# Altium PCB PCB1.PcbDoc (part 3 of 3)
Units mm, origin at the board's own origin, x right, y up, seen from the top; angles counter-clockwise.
Board outline 200.72 x 147.2 mm, 4 copper layers (L1 - TOP, L2 - GND, L3 - PWR, L4 - BOTTOM), stack 1.251 mm thick; 298 components, 161 nets, 911 pads, 474 vias.
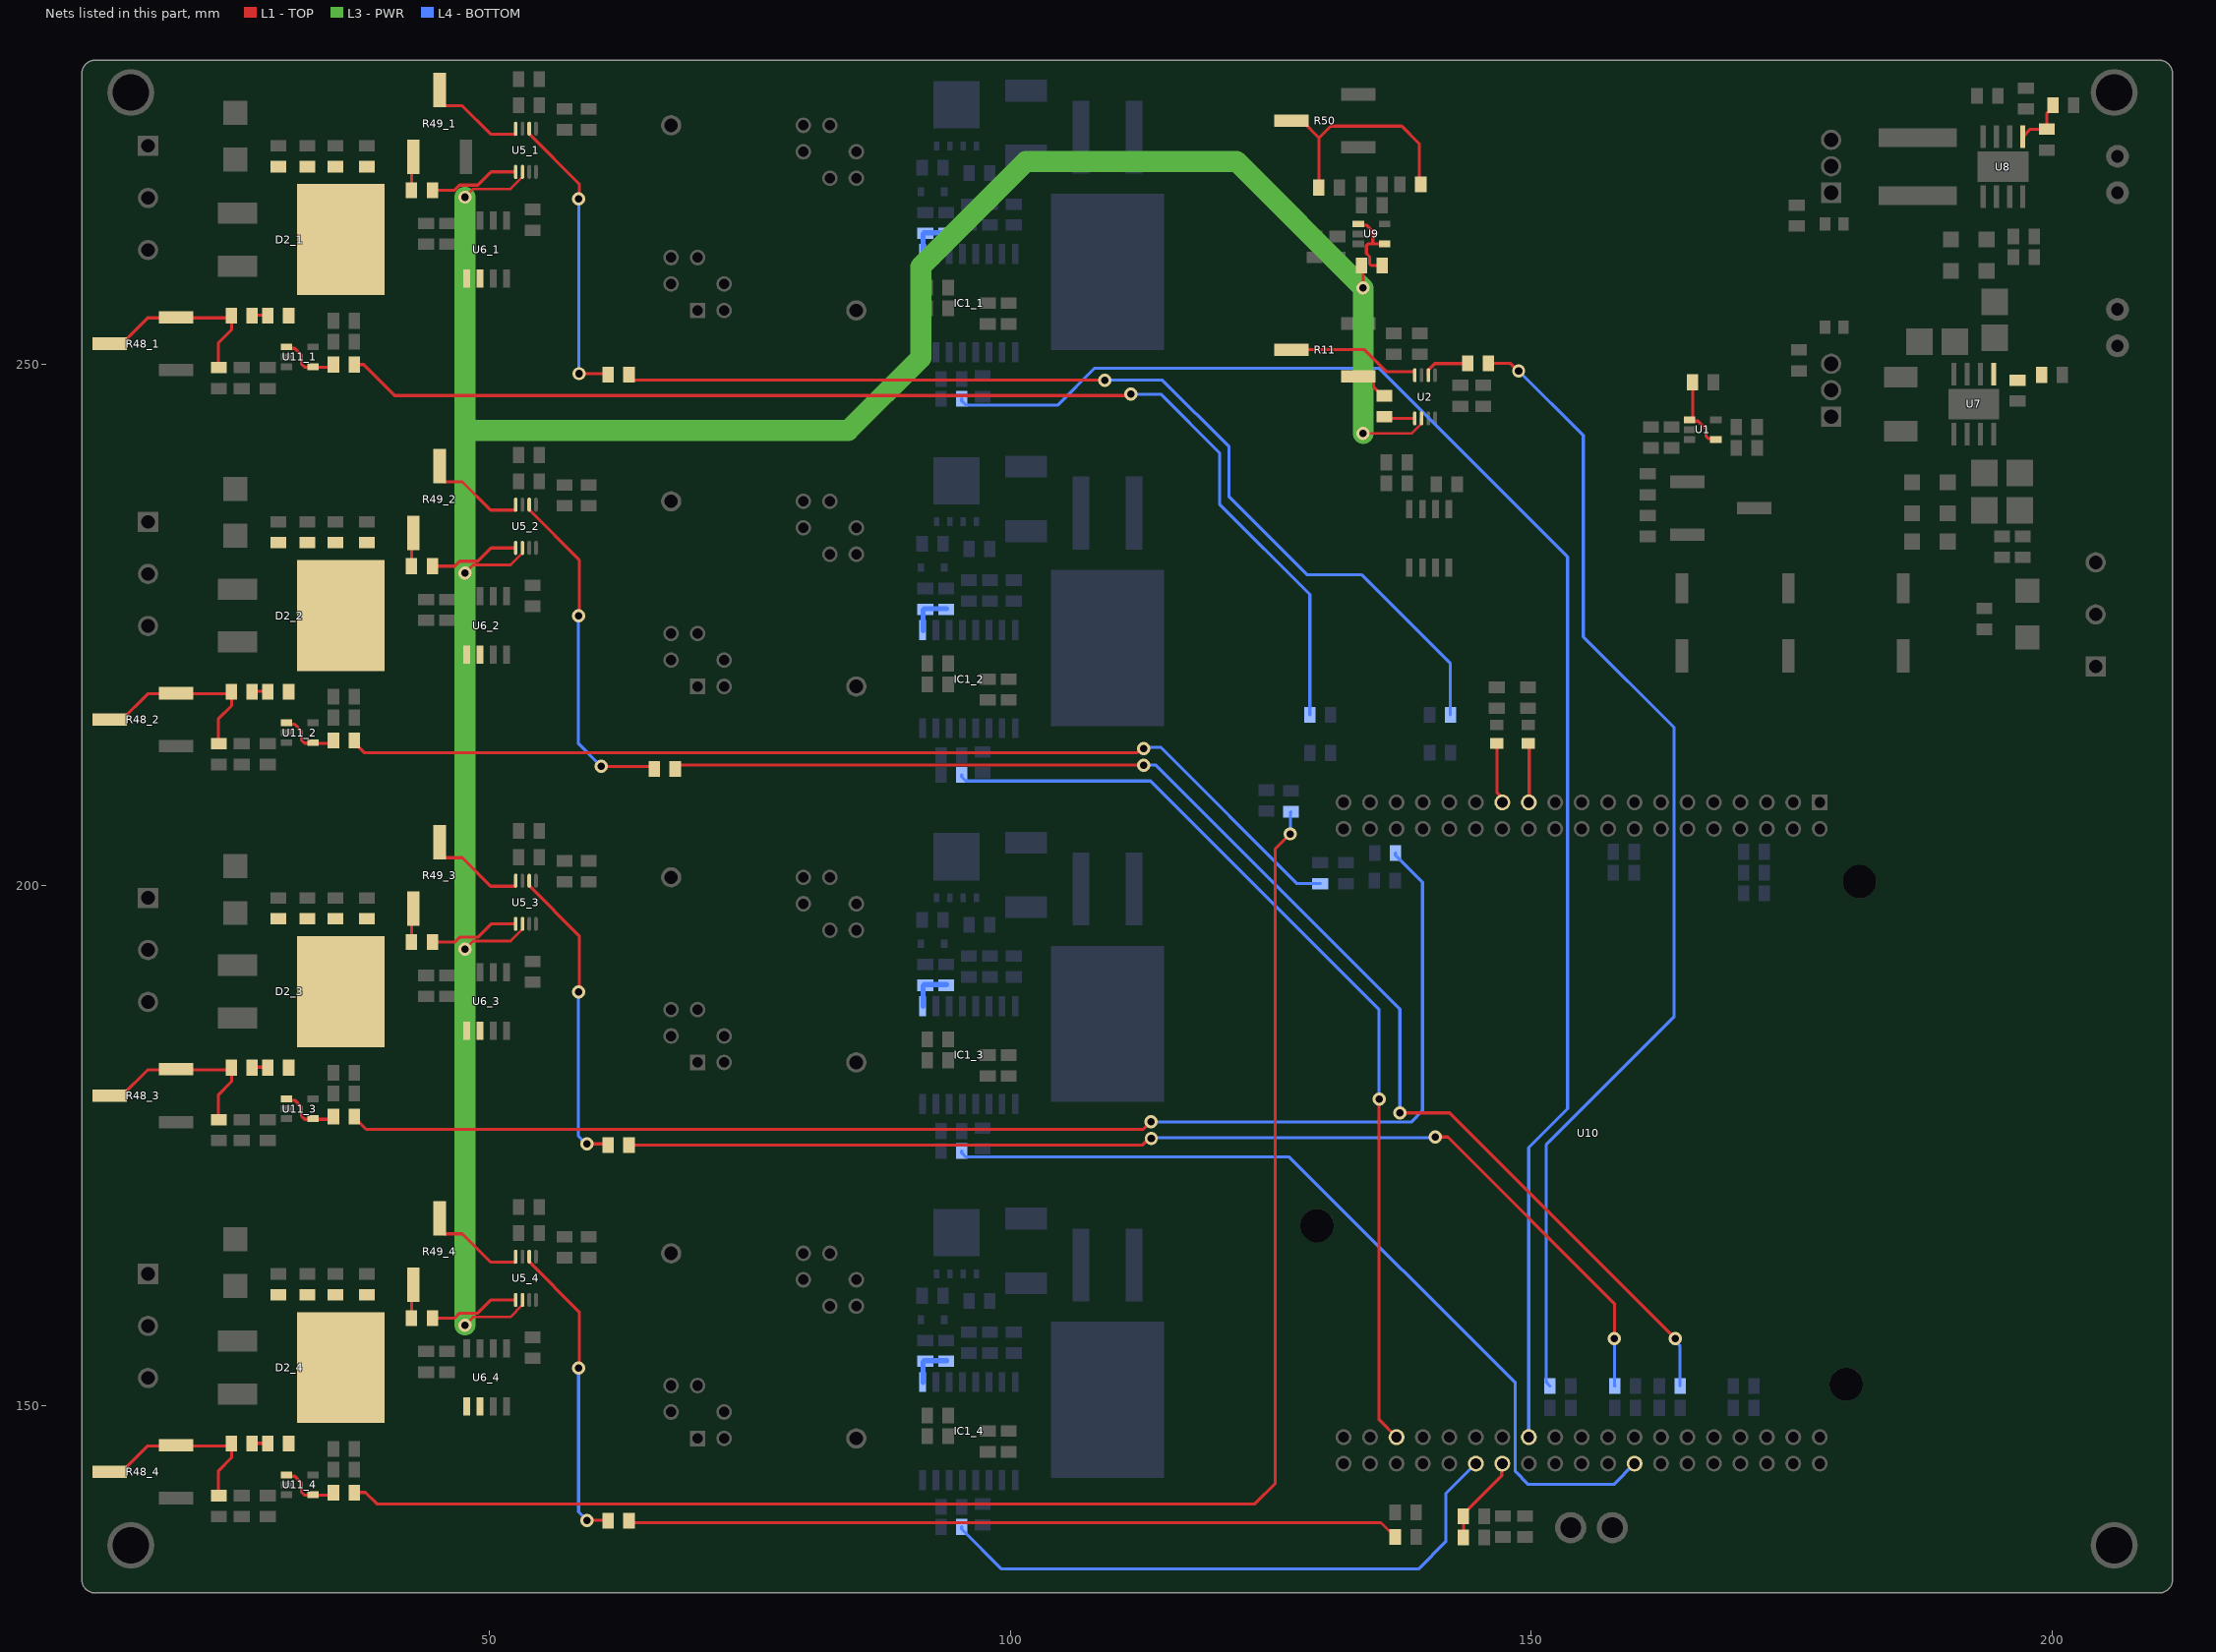
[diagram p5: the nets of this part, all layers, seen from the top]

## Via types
v1: diameter 0.8, hole 0.4, L1 - TOP to L4 - BOTTOM, tented both sides, 312 vias
v2: diameter 1.27, hole 0.711, L1 - TOP to L4 - BOTTOM, 150 vias
v3: diameter 0.63, hole 0.33, L1 - TOP to L4 - BOTTOM, 12 vias

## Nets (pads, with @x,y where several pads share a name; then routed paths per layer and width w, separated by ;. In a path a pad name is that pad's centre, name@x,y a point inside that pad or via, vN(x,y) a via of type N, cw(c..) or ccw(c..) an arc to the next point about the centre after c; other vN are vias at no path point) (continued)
NetR3_2: R3.2 U1.1 U1.4 | length 7.4
  L1 - TOP w0.3: U1.1@165.25,244.75 165.425,244.575 166.025,244.575 166.8,243.8 166.8,243.076 166.976,242.9 167.735,242.9 U1.4@167.79,242.845 ; U1.1@165.325,244.75 165.5,244.925 R3.2@165.5,248.3
NetR6_1: R6.1 R11.1 | length 3.7
  L1 - TOP w0.3: R11.1@133.375,248.91 134.43,248.91 134.875,248.465 134.875,247.813 135.688,247 R6.1@135.9,247
NetR6_2: R6.2 U2.1 | length 3
  L1 - TOP w0.3: R6.2@135.9,245 136.075,244.825 U2.1@138.825,244.825
NetR7_1: R7.1 R8.2 | length 112.1
  L1 - TOP w0.3: R7.1@145.925,250.125 147.991,250.125 148.716,249.4 v2(148.8,249.4)
  L4 - BOTTOM w0.3: v2(148.8,249.4) 155,243.2 155,223.85 163.725,215.125 163.725,187.375 151.45,175.1 151.45,152.25 R8.2@151.8,151.9
NetR7_2: R7.2 U2.6 | length 4.5
  L1 - TOP w0.3: U2.6@140.125,248.975 140.125,249.475 140.75,250.1 R7.2@143.9,250.1
NetR11_2: R11.2 U2.8 | length 13.1
  L1 - TOP w0.3: R11.2@126.975,251.45 133.95,251.45 136.075,249.325 138.802,249.325 138.825,249.302 U2.8@138.825,248.975
NetR13_1_2: R13_1.2 U10.CN10_23 | length 153.6
  L4 - BOTTOM w0.3: R13_1.2@95.325,246.7 95.325,246.51 95.725,246.11 104.56,246.11 108.1,249.65 135.375,249.65 153.5,231.525 153.5,178.532 149.77,174.802 U10.CN10_23@149.77,146.99
NetR13_2_2: R13_2.2 U10.CN10_33 | length 91.3
  L1 - TOP w0.3: v2(135.4,179.45) 135.4,148.66 U10.CN10_33@137.07,146.99
  L4 - BOTTOM w0.3: R13_2.2@95.325,210.59 95.325,210.4 95.725,210 113.46,210 135.4,188.06 v2(135.4,179.45)
NetR13_3_2: R13_3.2 U10.CN10_16 | length 83.8
  L4 - BOTTOM w0.3: R13_3.2@95.325,174.48 95.325,174.29 95.725,173.89 126.785,173.89 148.475,152.2 148.475,143.7 149.725,142.45 157.93,142.45 U10.CN10_16@159.93,144.45
NetR13_4_2: R13_4.2 U10.CN10_28 | length 58.1
  L4 - BOTTOM w0.3: R13_4.2@95.325,138.37 95.325,138.158 99.159,134.324 139.174,134.324 141.8,136.95 141.8,141.56 U10.CN10_28@144.69,144.45
NetR16_1_1: R16_1.1 R17_1.2 | length 1.6
  L1 - TOP w0.3: R17_1.2@27.228,254.734 R16_1.1@28.791,254.734
NetR16_2_1: R16_2.1 R17_2.2 | length 1.6
  L1 - TOP w0.3: R17_2.2@27.228,218.624 R16_2.1@28.791,218.624
NetR16_3_1: R16_3.1 R17_3.2 | length 1.6
  L1 - TOP w0.3: R17_3.2@27.228,182.514 R16_3.1@28.791,182.514
NetR16_4_1: R16_4.1 R17_4.2 | length 1.6
  L1 - TOP w0.3: R17_4.2@27.228,146.404 R16_4.1@28.791,146.404
NetR17_1_1: R17_1.1 R20_1.2 R48_1.2 R48_1.3 | length 18.4
  L1 - TOP w0.3: R48_1.2@13.585,251.944 14.64,251.944 17.18,254.484 19.985,254.484 24.978,254.484 25.228,254.734 25.228,253.356 23.966,252.094 R20_1.2@23.966,249.686
NetR17_2_1: R17_2.1 R20_2.2 R48_2.2 R48_2.3 | length 18.4
  L1 - TOP w0.3: R48_2.2@13.585,215.834 14.64,215.834 17.18,218.374 19.985,218.374 24.978,218.374 25.228,218.624 25.228,217.246 23.966,215.984 R20_2.2@23.966,213.576
NetR17_3_1: R17_3.1 R20_3.2 R48_3.2 R48_3.3 | length 18.4
  L1 - TOP w0.3: R48_3.2@13.585,179.724 14.64,179.724 17.18,182.264 19.985,182.264 24.978,182.264 25.228,182.514 25.228,181.136 23.966,179.874 R20_3.2@23.966,177.466
NetR17_4_1: R17_4.1 R20_4.2 R48_4.2 R48_4.3 | length 18.4
  L1 - TOP w0.3: R48_4.2@13.585,143.614 14.64,143.614 17.18,146.154 19.985,146.154 24.978,146.154 25.228,146.404 25.228,145.026 23.966,143.764 R20_4.2@23.966,141.356
NetR18_1_1: R18_1.1 R49_1.1 | length 3.3
  L1 - TOP w0.3: R18_1.1@42.5,266.75 42.5,269.79 R49_1.1@42.66,269.95
NetR18_1_2: R18_1.2 U5_1.1 | length 8.7
  L1 - TOP w0.3: R18_1.2@44.5,266.75 46.65,266.75 47.125,267.225 48.875,267.225 50.15,268.5 U5_1.1@52.5,268.5
NetR18_2_1: R18_2.1 R49_2.1 | length 3.3
  L1 - TOP w0.3: R18_2.1@42.5,230.64 42.5,233.68 R49_2.1@42.66,233.84
NetR18_2_2: R18_2.2 U5_2.1 | length 8.7
  L1 - TOP w0.3: R18_2.2@44.5,230.64 46.65,230.64 47.125,231.115 48.875,231.115 50.15,232.39 U5_2.1@52.5,232.39
NetR18_3_1: R18_3.1 R49_3.1 | length 3.3
  L1 - TOP w0.3: R18_3.1@42.5,194.53 42.5,197.57 R49_3.1@42.66,197.73
NetR18_3_2: R18_3.2 U5_3.1 | length 8.7
  L1 - TOP w0.3: R18_3.2@44.5,194.53 46.65,194.53 47.125,195.005 48.875,195.005 50.15,196.28 U5_3.1@52.5,196.28
NetR18_4_1: R18_4.1 R49_4.1 | length 3.3
  L1 - TOP w0.3: R18_4.1@42.5,158.42 42.5,161.46 R49_4.1@42.66,161.62
NetR18_4_2: R18_4.2 U5_4.1 | length 8.7
  L1 - TOP w0.3: R18_4.2@44.5,158.42 46.65,158.42 47.125,158.895 48.875,158.895 50.15,160.17 U5_4.1@52.5,160.17
NetR19_1_1: R19_1.1 R23_1.1 | length 115.5
  L1 - TOP w0.3: R19_1.1@37,250 37.9,250 40.875,247.025 111.425,247.025 v2(111.55,247.15)
  L4 - BOTTOM w0.3: v2(111.55,247.15) 114.45,247.15 120.075,241.525 120.075,236.6 128.75,227.925 R23_1.1@128.75,216.35
NetR19_1_2: R19_1.2 U11_1.1 U11_1.4 | length 5.9
  L1 - TOP w0.3: U11_1.1@30.558,251.639 30.633,251.564 31.281,251.564 31.933,250.911 31.933,250.036 32.226,249.743 33.088,249.743 33.098,249.734 34.683,249.734 34.983,250.034 R19_1.2@34.983,250.036
NetR19_2_1: R19_2.1 R23_2.1 | length 99
  L1 - TOP w0.3: R19_2.1@37,213.89 37,213.678 37.953,212.725 112.163,212.725 112.538,213.1 v2(112.8,213.1)
  L4 - BOTTOM w0.3: v2(112.8,213.1) 112.95,213.25 114.425,213.25 127.526,200.149 R23_2.1@129.75,200.149
NetR19_2_2: R19_2.2 U11_2.1 U11_2.4 | length 5.9
  L1 - TOP w0.3: U11_2.1@30.558,215.529 30.633,215.454 31.281,215.454 31.933,214.801 31.933,213.926 32.226,213.633 33.088,213.633 33.098,213.624 34.683,213.624 34.983,213.924 R19_2.2@34.983,213.926
NetR19_3_1: R19_3.1 R23_3.1 | length 129.7
  L1 - TOP w0.3: R19_3.1@37,177.78 37,177.7 38.15,176.55 112.75,176.55 v2(113.5,177.3)
  L4 - BOTTOM w0.3: v2(113.5,177.3) 113.55,177.25 138.475,177.25 139.575,178.35 139.575,200.279 136.975,202.879 R23_3.1@136.975,203.091
NetR19_3_2: R19_3.2 U11_3.1 U11_3.4 | length 5.9
  L1 - TOP w0.3: U11_3.1@30.558,179.419 30.633,179.344 31.281,179.344 31.933,178.691 31.933,177.816 32.226,177.523 33.088,177.523 33.098,177.514 34.683,177.514 34.983,177.814 R19_3.2@34.983,177.816
NetR19_4_1: R19_4.1 R23_4.1 | length 154.8
  L1 - TOP w0.3: R19_4.1@37,141.67 38.071,141.67 39.166,140.575 123.475,140.575 125.425,142.525 125.425,203.475 v2(126.875,204.925)
  L4 - BOTTOM w0.3: v2(126.875,204.925) 126.875,206.975 R23_4.1@126.95,207.05
NetR19_4_2: R19_4.2 U11_4.1 U11_4.4 | length 5.9
  L1 - TOP w0.3: U11_4.1@30.558,143.309 30.633,143.234 31.281,143.234 31.933,142.581 31.933,141.706 32.226,141.413 33.088,141.413 33.098,141.404 34.683,141.404 34.983,141.704 R19_4.2@34.983,141.706
NetR21_1_1: R21_1.1 R22_1.2 | length 98.2
  L1 - TOP w0.3: R21_1.1@63.379,249.033 63.379,248.9 63.779,248.5 v2(109.075,248.5)
  L4 - BOTTOM w0.3: v2(109.075,248.5) 114.6,248.5 121.002,242.098 121.002,237.298 128.475,229.825 133.7,229.825 142.25,221.275 R22_1.2@142.25,216.35
NetR21_1_2: R21_1.2 U5_1.6 | length 28.4
  L1 - TOP w0.3: U5_1.6@53.8,272.65 53.8,272.15 58.6,267.35 58.6,265.975 v2(58.525,265.9) ; v2(58.575,249.125) 61.287,249.125 R21_1.2@61.379,249.033
  L4 - BOTTOM w0.3: v2(58.525,265.9) 58.55,265.875 58.55,249.15 v2(58.575,249.125)
NetR21_2_1: R21_2.1 R22_2.2 | length 129.5
  L1 - TOP w0.3: R21_2.1@67.85,211.225 68.15,211.525 v2(112.775,211.525) ; v2(137.4,178.125) 142.175,178.125 v2(163.85,156.45)
  L4 - BOTTOM w0.3: v2(112.775,211.525) 113.975,211.525 137.4,188.1 v2(137.4,178.125) ; v2(163.85,156.45) 163.85,156.188 164.3,155.738 R22_2.2@164.3,151.9
NetR21_2_2: R21_2.2 U5_2.6 | length 33.2
  L1 - TOP w0.3: U5_2.6@53.8,236.54 53.8,236.04 58.6,231.24 58.6,225.94 v2(58.525,225.865) ; v2(60.7,211.4) 65.675,211.4 R21_2.2@65.825,211.25
  L4 - BOTTOM w0.3: v2(58.525,225.865) 58.525,213.575 v2(60.7,211.4)
NetR21_3_1: R21_3.1 R22_3.2 | length 109.2
  L1 - TOP w0.3: R21_3.1@63.649,175.025 112.641,175.025 113.291,175.675 v2(113.525,175.675) ; v2(140.8,175.825) 142,175.825 158,159.825 v2(158,156.475)
  L4 - BOTTOM w0.3: v2(113.525,175.675) 113.6,175.75 140.725,175.75 v2(140.8,175.825) ; v2(158,156.475) 158,151.925 R22_3.2@158.025,151.9
NetR21_3_2: R21_3.2 U5_3.6 | length 29.4
  L1 - TOP w0.3: U5_3.6@53.8,200.43 53.8,199.93 58.6,195.13 58.6,189.83 v2(58.525,189.755) ; v2(59.35,175.15) 61.254,175.15 R21_3.2@61.379,175.025
  L4 - BOTTOM w0.3: v2(58.525,189.755) 58.525,175.884 v2@59.066,175.343
NetR21_4_1: R21_4.1 R22_4.2 | length 73.9
  L1 - TOP w0.3: R21_4.1@63.625,138.775 135.575,138.775 R22_4.2@136.95,137.4
NetR21_4_2: R21_4.2 U5_4.6 | length 30
  L1 - TOP w0.3: U5_4.6@53.8,164.32 53.8,163.82 58.6,159.02 58.6,153.72 v2(58.525,153.645) ; v2(59.35,139) 61.575,139 R21_4.2@61.625,138.95
  L4 - BOTTOM w0.3: v2(58.525,153.645) 58.538,153.633 58.538,139.812 v2(59.35,139)
NetR31_1: R31.1 R32.2 U7.5
NetR33_1: R33.1 R35.2 R50.2 | length 22.9
  L1 - TOP w0.3: R50.2@126.975,273.36 128.03,273.36 129.625,271.765 ; R35.2@129.625,267 129.625,271.765 ; R33.1@139.45,267.275 139.25,267.475 139.25,271.225 137.575,272.9 130.76,272.9 129.625,271.765
NetR34_1: R34.1 R38.2 U8.5 | length 5.2
  L1 - TOP w0.3: U8.5@197.205,271.875 197.93,272.6 R38.2@199.5,272.6 199.5,274.112 199.676,274.288 199.7,274.288 200.1,274.688 R34.1@200.1,274.9
NetR36_1: R36.1 U9.1 U9.4 | length 8.2
  L1 - TOP w0.3: U9.1@133.328,263.471 133.403,263.396 134.179,263.396 134.8,262.775 134.8,261.595 ; R36.1@135.7,259.5 134.666,259.5 134.49,259.676 134.49,260.361 134.19,260.661 134.19,261.419 134.366,261.595 134.8,261.595 ; U9.4@135.758,261.413 U9.4@135.94,261.595 134.8,261.595
NetR49_1_2: R49_1.2 U5_1.8 | length 9.6
  L1 - TOP w0.3: R49_1.2@45.2,276.35 45.2,275.295 45.645,274.85 47.375,274.85 50.1,272.125 52.377,272.125 U5_1.8@52.4,272.102
NetR49_2_2: R49_2.2 U5_2.8 | length 9.6
  L1 - TOP w0.3: R49_2.2@45.2,240.24 45.2,239.185 45.645,238.74 47.375,238.74 50.1,236.015 52.377,236.015 U5_2.8@52.4,235.992
NetR49_3_2: R49_3.2 U5_3.8 | length 9.6
  L1 - TOP w0.3: R49_3.2@45.2,204.13 45.2,203.075 45.645,202.63 47.375,202.63 50.1,199.905 52.377,199.905 U5_3.8@52.4,199.882
NetR49_4_2: R49_4.2 U5_4.8 | length 9.6
  L1 - TOP w0.3: R49_4.2@45.2,168.02 45.2,166.965 45.645,166.52 47.375,166.52 50.1,163.795 52.377,163.795 U5_4.8@52.4,163.772
PWM_GATE_1: IC1_1.1 R12_1.2 R14_1.2 | length 4.3
  L4 - BOTTOM w0.5: IC1_1.1@91.613,260.576 91.613,262.533 91.741,262.661 R12_1.2@93.866,262.661
PWM_GATE_2: IC1_2.1 R12_2.2 R14_2.2 | length 4.3
  L4 - BOTTOM w0.5: IC1_2.1@91.613,224.466 91.613,226.423 91.741,226.551 R12_2.2@93.866,226.551
PWM_GATE_3: IC1_3.1 R12_3.2 R14_3.2 | length 4.3
  L4 - BOTTOM w0.5: IC1_3.1@91.613,188.356 91.613,190.313 91.741,190.441 R12_3.2@93.866,190.441
PWM_GATE_4: IC1_4.1 R12_4.2 R14_4.2 | length 4.3
  L4 - BOTTOM w0.5: IC1_4.1@91.613,152.246 91.613,154.203 91.741,154.331 R12_4.2@93.866,154.331
REF_HALL: R36.2 U2.2 U5_1.2 U5_2.2 U5_3.2 U5_4.2 | length 265.5
  L1 - TOP w0.25: v2(47.625,157.745) 48.41,158.53 52.01,158.53 53.15,159.67 U5_4.2@53.15,160.17 ; v2(47.625,193.855) 48.41,194.64 52.01,194.64 53.15,195.78 U5_3.2@53.15,196.28 ; v2(47.625,229.965) 48.41,230.75 52.01,230.75 53.15,231.89 U5_2.2@53.15,232.39 ; v2(47.625,266.075) 48.41,266.86 52.01,266.86 53.15,268 U5_1.2@53.15,268.5 ; R36.2@133.7,259.525 133.875,259.35 v2(133.875,257.35) ; v2(133.875,243.375) 138.525,243.375 139.442,244.292 139.442,244.792 U2.2@139.475,244.825
  L3 - PWR w2: v2(47.625,157.745) v2(47.625,193.855) v2(47.625,229.965) 47.625,243.679 ; v2(47.625,266.075) 47.625,243.679 ; v2(133.875,243.375) v2(133.875,257.35) 121.725,269.5 101.5,269.5 91.4,259.4 91.4,250.625 84.454,243.679 47.625,243.679
TEMP_ADC: C60.1 R42.1 U10.CN10_26 | length 8.7
  L1 - TOP w0.3: C60.1@143.5,137.4 R42.1@143.5,139.4 143.5,139.612 147.176,143.288 147.176,144.396 U10.CN10_26@147.28,144.5
USR_LED_0: D6.K U10.CN7_23 | length 5.7
  L1 - TOP w0.3: D6.K@149.708,213.657 149.82,213.545 U10.CN7_23@149.82,208
USR_LED_1: D8.K U10.CN7_25 | length 5.9
  L1 - TOP w0.3: D8.K@146.708,213.657 146.708,208.903 147.28,208.331 U10.CN7_25@147.28,208
VLEAF_IN_1: C18_1.1 C19_1.1 C20_1.1 C21_1.1 D2_1.K R16_1.2 U6_1.1 U6_1.2
VLEAF_IN_2: C18_2.1 C19_2.1 C20_2.1 C21_2.1 D2_2.K R16_2.2 U6_2.1 U6_2.2
VLEAF_IN_3: C18_3.1 C19_3.1 C20_3.1 C21_3.1 D2_3.K R16_3.2 U6_3.1 U6_3.2
VLEAF_IN_4: C18_4.1 C19_4.1 C20_4.1 C21_4.1 D2_4.K R16_4.2 U6_4.1 U6_4.2
pads on no net: IC1_1.4 IC1_1.5 IC1_1.9 IC1_1.10 IC1_1.16 IC1_2.4 IC1_2.5 IC1_2.9 IC1_2.10 IC1_2.16 IC1_3.4 IC1_3.5 IC1_3.9 IC1_3.10 IC1_3.16 IC1_4.4 IC1_4.5 IC1_4.9 IC1_4.10 IC1_4.16 J1.2 J2_1.2 J2_2.2 J2_3.2 J2_4.2 R10.3 R11.3 R49_1.3 R49_2.3 R49_3.3 R49_4.3 R50.3 U4_1.13 U4_1.14 U4_2.13 U4_2.14 U4_3.13 U4_3.14 U4_4.13 U4_4.14 U7.4 U8.4 U10. U10.CN7_1 U10.CN7_2 U10.CN7_3 U10.CN7_4 U10.CN7_5 U10.CN7_7 U10.CN7_9 U10.CN7_10 U10.CN7_11 U10.CN7_12 U10.CN7_13 U10.CN7_14 U10.CN7_15 U10.CN7_17 U10.CN7_18 U10.CN7_21 U10.CN7_24 U10.CN7_26 U10.CN7_27 U10.CN7_28 U10.CN7_29 U10.CN7_30 U10.CN7_31 U10.CN7_33 U10.CN7_34 U10.CN10_1 U10.CN10_2 U10.CN10_3 U10.CN10_4 U10.CN10_5 U10.CN10_7 U10.CN10_8 U10.CN10_10 U10.CN10_11 U10.CN10_12 U10.CN10_14 U10.CN10_17 U10.CN10_18 U10.CN10_19 U10.CN10_21 U10.CN10_24 U10.CN10_25 U10.CN10_27 U10.CN10_29 U10.CN10_30 U10.CN10_31 U10.CN10_35 U10.CN10_36 U10.CN10_37 U10.CN10_38

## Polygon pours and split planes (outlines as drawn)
NetD3_3_1,2 on L4 - BOTTOM "NONET_L-01_P-001" (solid, pour order 778): 78.875,196.845 81.315,194.405 90.03,194.405 90.55,194.925 90.55,199.2 90.825,199.475 103.5,199.475 104.15,198.825 104.15,195.85 104.445,195.555 113.805,195.555 114.575,196.325 114.575,208.125 113.6,209.1 80,209.1 78.875,207.975
NetD3_1_1,2 on L4 - BOTTOM "NONET_L-01_P-001" (solid, pour order 775): 78.875,269.065 81.315,266.625 87.125,266.625 90.45,269.95 90.45,271.25 90.95,271.75 103.65,271.75 104.3,271.1 104.3,268.175 104.7,267.775 118.025,267.775 119.025,268.775 119.025,277.525 118.3,278.25 79.35,278.25 78.875,277.775
CO_STACK_IN on L4 - BOTTOM "NONET_L-01_P-001" (solid, pour order 784): 113.187,266.575 124.425,266.575 124.925,266.075 124.925,251.875 124.475,251.425 113.15,251.425
CO_STACK_IN on L4 - BOTTOM "NONET_L-01_P-001" (solid, pour order 786): 113.762,158.075 125,158.075 125.5,157.575 125.5,143.375 125.2,143.075 113.726,143.075
CO_STACK_IN on L4 - BOTTOM "NONET_L-01_P-001" (solid, pour order 785): 113.637,194.2 124.875,194.2 125.375,193.7 125.375,179.5 124.925,179.05 113.6,179.05
CO_STACK_IN on L4 - BOTTOM "NONET_L-01_P-001" (solid, pour order 698): 113.112,230.45 124.35,230.45 124.85,229.95 124.85,215.75 124.4,215.3 113.075,215.3
NetD4_4_2 on L4 - BOTTOM "NONET_L-01_P-001" (solid, pour order 745): 90.995,157.495 90.833,157.657 90.833,159.92 92.45,159.92 92.45,159.62 91.925,159.095 91.925,157.62 91.8,157.495
GND on L4 - BOTTOM "NONET_L-01_P-001" (solid, pour order 696): 95.308,156.431 94.92,156.819 94.92,159.206 96.608,159.206 96.808,159.406 97.358,158.856 102.883,158.856 103.408,158.331 103.408,157.231 102.608,156.431
GND on L4 - BOTTOM "NONET_L-01_P-001" (solid, pour order 692): 96.808,159.406 96.608,159.206 93.233,159.206 92.933,159.506 92.933,161.306 93.133,161.506 93.583,161.506 93.858,161.781 93.858,163.006 94.108,163.256 97.058,163.256 97.283,163.031 97.283,161.256 96.808,160.781
NetD4_4_2 on L4 - BOTTOM "NONET_L-01_P-001" (solid, pour order 688): 90.683,159.931 90.983,159.631 92.258,159.631 92.483,159.856 92.483,161.606 92.808,161.931 93.333,161.931 93.558,162.156 93.558,162.981 93.283,163.256 91.058,163.256 90.683,162.906
NetC22_4_1 on L4 - BOTTOM "NONET_L-01_P-001" (solid, pour order 684): 97.508,159.281 97.683,159.106 103.633,159.106 104.058,159.531 104.058,162.706 103.583,163.181 99.458,163.181 98.583,162.306 98.583,161.231 98.258,160.906 97.358,160.906 97.141,160.689 97.141,159.573
NetD3_4_1,2 on L4 - BOTTOM "NONET_L-01_P-001" (solid, pour order 777): 78.875,160.735 81.315,158.295 90.22,158.295 90.425,158.5 90.425,162.975 90.875,163.425 103.675,163.425 104.225,162.875 104.225,159.8 104.58,159.445 113.075,159.445 113.525,159.895 113.525,172.375 112.7,173.2 79.775,173.2 78.875,172.3
NetD4_3_2 on L4 - BOTTOM "NONET_L-01_P-001" (solid, pour order 744): 90.995,193.605 90.833,193.767 90.833,196.03 92.45,196.03 92.45,195.73 91.925,195.205 91.925,193.73 91.8,193.605
GND on L4 - BOTTOM "NONET_L-01_P-001" (solid, pour order 695): 95.308,192.541 94.92,192.929 94.92,195.316 96.608,195.316 96.808,195.516 97.358,194.966 102.883,194.966 103.408,194.441 103.408,193.341 102.608,192.541
GND on L4 - BOTTOM "NONET_L-01_P-001" (solid, pour order 691): 96.808,195.516 96.608,195.316 93.233,195.316 92.933,195.616 92.933,197.416 93.133,197.616 93.583,197.616 93.858,197.891 93.858,199.116 94.108,199.366 97.058,199.366 97.283,199.141 97.283,197.366 96.808,196.891
NetD4_3_2 on L4 - BOTTOM "NONET_L-01_P-001" (solid, pour order 687): 90.683,196.041 90.983,195.741 92.258,195.741 92.483,195.966 92.483,197.716 92.808,198.041 93.333,198.041 93.558,198.266 93.558,199.091 93.283,199.366 91.058,199.366 90.683,199.016
NetC22_3_1 on L4 - BOTTOM "NONET_L-01_P-001" (solid, pour order 683): 97.508,195.391 97.683,195.216 103.633,195.216 104.058,195.641 104.058,198.816 103.583,199.291 99.458,199.291 98.583,198.416 98.583,197.341 98.258,197.016 97.358,197.016 97.141,196.799 97.141,195.683
NetD4_2_2 on L4 - BOTTOM "NONET_L-01_P-001" (solid, pour order 743): 90.995,229.715 90.833,229.877 90.833,232.14 92.45,232.14 92.45,231.84 91.925,231.315 91.925,229.84 91.8,229.715
GND on L4 - BOTTOM "NONET_L-01_P-001" (solid, pour order 694): 95.308,228.651 94.92,229.039 94.92,231.426 96.608,231.426 96.808,231.626 97.358,231.076 102.883,231.076 103.408,230.551 103.408,229.451 102.608,228.651
GND on L4 - BOTTOM "NONET_L-01_P-001" (solid, pour order 690): 96.808,231.626 96.608,231.426 93.233,231.426 92.933,231.726 92.933,233.526 93.133,233.726 93.583,233.726 93.858,234.001 93.858,235.226 94.108,235.476 97.058,235.476 97.283,235.251 97.283,233.476 96.808,233.001
NetD4_2_2 on L4 - BOTTOM "NONET_L-01_P-001" (solid, pour order 686): 90.683,232.151 90.983,231.851 92.258,231.851 92.483,232.076 92.483,233.826 92.808,234.151 93.333,234.151 93.558,234.376 93.558,235.201 93.283,235.476 91.058,235.476 90.683,235.126
NetC22_2_1 on L4 - BOTTOM "NONET_L-01_P-001" (solid, pour order 682): 97.508,231.501 97.683,231.326 103.633,231.326 104.058,231.751 104.058,234.926 103.583,235.401 99.458,235.401 98.583,234.526 98.583,233.451 98.258,233.126 97.358,233.126 97.141,232.909 97.141,231.793
NetD3_2_1,2 on L4 - BOTTOM "NONET_L-01_P-001" (solid, pour order 776): 78.875,232.955 81.315,230.515 89.84,230.515 90.5,231.175 90.5,235.125 91.05,235.675 103.5,235.675 104.2,234.975 104.2,232.2 104.735,231.665 115.765,231.665 116.375,232.275 116.375,244.2 115.05,245.525 80.5,245.525 78.875,243.9
NetC22_1_1 on L4 - BOTTOM "NONET_L-01_P-001" (solid, pour order 681): 97.508,267.611 97.683,267.436 103.633,267.436 104.058,267.861 104.058,271.036 103.583,271.511 99.458,271.511 98.583,270.636 98.583,269.561 98.258,269.236 97.358,269.236 97.141,269.019 97.141,267.903
NetD4_1_2 on L4 - BOTTOM "NONET_L-01_P-001" (solid, pour order 685): 90.683,268.261 90.983,267.961 92.258,267.961 92.483,268.186 92.483,269.936 92.808,270.261 93.333,270.261 93.558,270.486 93.558,271.311 93.283,271.586 91.058,271.586 90.683,271.236
GND on L4 - BOTTOM "NONET_L-01_P-001" (solid, pour order 689): 96.808,267.736 96.608,267.536 93.233,267.536 92.933,267.836 92.933,269.636 93.133,269.836 93.583,269.836 93.858,270.111 93.858,271.336 94.108,271.586 97.058,271.586 97.283,271.361 97.283,269.586 96.808,269.111
GND on L4 - BOTTOM "NONET_L-01_P-001" (solid, pour order 693): 95.308,264.761 94.92,265.149 94.92,267.536 96.608,267.536 96.808,267.736 97.358,267.186 102.883,267.186 103.408,266.661 103.408,265.561 102.608,264.761
NetD4_1_2 on L4 - BOTTOM "NONET_L-01_P-001" (solid, pour order 742): 90.995,265.825 90.833,265.987 90.833,268.25 92.45,268.25 92.45,267.95 91.925,267.425 91.925,265.95 91.8,265.825
GND on L4 - BOTTOM "NONET_L-01_P-001" (solid, pour order 750): 163.575,150.525 163.725,150.675 170,150.675 170.125,150.55 170.125,148.95 170,148.825 168.95,148.825 168.6,148.475 168.6,146.15 168.375,145.925 166.725,145.925 166.575,146.075 166.575,148.525 166.4,148.7 163.725,148.7 163.575,148.85
GND on L4 - BOTTOM "NONET_L-01_P-001" (solid, pour order 749): 169.15,206 169.525,206.375 170.925,206.375 171.175,206.125 171.175,200.5 170.975,200.3 169.7,200.3 169.15,200.85
NetC55_2 on L4 - BOTTOM "NONET_L-01_P-001" (solid, pour order 748): 171.9,198.3 173.075,198.3 173.175,198.4 173.175,204.3 173.7,204.825 173.7,205.975 173.3,206.375 171.9,206.375 171.6,206.075 171.6,198.6 171.675,198.525
GND on L4 - BOTTOM "NONET_L-01_P-001" (solid, pour order 747): 153.95,206.025 154.25,206.325 155.525,206.325 155.825,206.025 155.825,204.675 156.2,204.3 158.45,204.3 158.675,204.075 158.675,200.375 158.45,200.15 157,200.15 156.75,200.4 156.75,203.1 156.45,203.4 154.325,203.4 153.95,203.775
3V3 on L4 - BOTTOM "NONET_L-01_P-001" (solid, pour order 746): 159.25,200.125 160.675,200.125 160.925,200.375 160.925,205.975 160.4,206.5 159.475,206.5 159.025,206.05 159.025,200.35
GND on L1 - TOP "NONET_L-01_P-001" (solid, pour order 680): 210.65,209.75 211.025,210.125 211.025,224.25 210.525,224.75 203.6,224.75 202.9,225.45 159.975,225.45 159.975,211.65 161.875,209.75
GND on L1 - TOP "NONET_L-01_P-001" (solid, pour order 677): 190.05,247.675 189.8,247.425 183.35,247.425 183.1,247.675 183.1,249.875 184.95,251.725 184.95,253.8 185.6,254.45 195.8,254.45 195.8,256.95 195.475,257.275 186.55,257.275 180.925,251.65 180.925,245.325 181.175,245.075 188.4,245.075 189.175,244.3 189.175,231.575 189.375,231.375 191.05,231.375 192.55,232.875 198.025,232.875 198.2,233.05 198.2,234 197.95,234.25 195.1,234.25 194.864,234.486 194.864,240.786 194.55,241.1 191.425,241.1 191.225,241.3 191.225,244.75 201.375,244.75 201.6,244.975 201.6,247.45 201.2,247.85 198.525,247.85 198.375,247.7 198.375,247.25 198.175,247.05 195.6,247.05 194.95,247.7
LIPO on L1 - TOP "NONET_L-01_P-001" (solid, pour order 729): 140.5,231.4 167.9,231.4 168.475,230.825 168.475,226.825 167.35,225.7 140.95,225.7 140.5,226.15
VLEAF_IN_1 on L1 - TOP "NONET_L-01_P-001" (solid, pour order 657): 30.233,253.711 31.283,253.711 31.583,254.011 31.583,255.911 31.958,256.286 40.033,256.286 40.408,256.661 40.408,268.561 39.158,269.811 29.058,269.811 29.058,268.211 29.558,267.711 29.558,256.636 30.233,255.961
LIPO on L1 - TOP "LIPO_L01_P740" (solid, pour order 740): 195.85,239.975 198.4,239.975 198.4,235.3 199.425,234.275 200.88,234.275 200.88,233.63 200.475,233.225 198.676,233.816 197.743,234.7 196.45,234.7 195.85,235.3
LIPO on L1 - TOP "NONET_L-01_P-001" (solid, pour order 787): 191.45,242.175 191.45,241.375 191.6,241.225 194.7,241.225 195.147,240.778 195.147,234.445 198.03,234.445 198.625,233.85 200.2,233.85 201.375,235.025 201.375,241.7 201.05,242.025 193.8,242.025 193.6,242.225 193.6,242.425 191.7,242.425
GND on L1 - TOP "NONET_L-01_P-001" (solid, pour order 712): 134.225,240.325 135.4,241.5 136.7,241.5 136.8,241.4 136.8,235 137.2,234.6 141.2,234.6 141.6,235 141.6,236.9 142.3,237.6 142.3,239.2 142.5,239.4 143.5,239.4 143.7,239.2 143.7,232.2 143.5,232 139.4,232 138,232 134.225,235.775
CO_STACK_IN on L1 - TOP "NONET_L-01_P-001" (solid, pour order 781): 114.725,143.125 123.975,143.125 124.875,144.025 124.875,265.4 123.7,266.575 114.725,266.575
CO_STACK_IN on L1 - TOP "NONET_L-01_P-001" (solid, pour order 780): 124.75,244.75 138.125,231.375 138.125,227.225 124.45,213.55 122.85,213.55 118.975,217.425 118.975,240 123.725,244.75
GND on L1 - TOP "NONET_L-01_P-001" (solid, pour order 779): 196.45,276 196.683,275.767 198.262,275.767 198.55,276.055 198.55,276.975 198.25,277.275 196.825,277.275 196.45,276.9
VLEAF_IN_4 on L1 - TOP "NONET_L-01_P-001" (solid, pour order 660): 30.233,145.381 31.283,145.381 31.583,145.681 31.583,147.581 31.958,147.956 40.033,147.956 40.408,148.331 40.408,160.231 39.158,161.481 29.058,161.481 28.533,160.956 28.533,160.406 29.558,159.381 29.558,148.306 30.233,147.631
NetD2_4_A on L1 - TOP "NONET_L-01_P-001" (solid, pour order 656): 22.008,154.656 23.233,155.881 23.233,161.756 24.408,162.931 27.458,162.931 28.208,162.181 28.208,149.931 27.958,149.681 15.158,149.681 14.783,150.056 14.783,154.231 15.208,154.656
GND on L1 - TOP "NONET_L-01_P-001" (solid, pour order 668): 25.529,140.356 25.283,140.602 25.283,144.006 25.958,144.681 29.233,144.681 29.858,144.056 29.858,142.906 30.008,142.756 31.158,142.756 31.408,142.506 31.408,142.106 31.283,141.981 29.858,141.981 29.608,141.731 29.608,140.881 29.083,140.356
GND on L1 - TOP "NONET_L-01_P-001" (solid, pour order 664): 12.125,163.939 12.125,168.72 13.786,170.381 38.533,170.381 40.008,168.906 40.008,162.831 39.183,162.006 29.008,162.006 28.583,162.431 28.583,163.481 28.083,163.981 24.308,163.981 21.033,160.706 15.358,160.706
+5V on L1 - TOP "NONET_L-01_P-001" (solid, pour order 754): 40.875,155.545 41.85,156.52 48.175,156.52 48.3,156.395 48.3,154.72 48.075,154.495 41.25,154.495 40.875,154.87
GND on L1 - TOP "NONET_L-01_P-001" (solid, pour order 758): 54.225,160.795 54.325,160.895 54.6,160.895 54.7,160.795 54.7,159.32 56.725,157.295 56.725,152.045 56.275,151.595 42.975,151.595 42.6,151.97 42.6,153.57 43,153.97 50.725,153.97 51.125,154.37 51.125,156.42 51.2,156.495 52,156.495 52.1,156.395 52.1,155.47 52.3,155.27 54.65,155.27 55.15,155.77 55.15,157.32 54.225,158.245
GND on L1 - TOP "NONET_L-01_P-001" (solid, pour order 762): 54.1,165.77 54.3,165.57 60.45,165.57 60.7,165.82 60.7,169.345 59.975,170.07 54.2,170.07 54.1,169.97
3V3 on L1 - TOP "NONET_L-01_P-001" (solid, pour order 766): 50.225,169.745 50.525,170.045 53.25,170.045 53.425,169.87 53.425,163.62 53.3,163.495 53,163.495 52.925,163.57 52.925,165.32 52.65,165.595 50.35,165.595 50.225,165.72
HALL_OUT_4 on L1 - TOP "NONET_L-01_P-001" (solid, pour order 770): 49.9,150.795 50.125,151.02 64.675,151.02 66.975,153.32 71.125,153.32 74.15,150.295 74.15,143.07 73.055,141.975 50.475,141.975 49.9,142.55
VLEAF_IN_4 on L1 - TOP "NONET_L-01_P-001" (solid, pour order 774): 49.525,150.77 49.325,150.97 40.95,150.97 40.3,151.62 39.3,151.62 38.825,151.145 38.825,148.27 39.139,147.956 49.261,147.956 49.525,148.22
VLEAF_IN_3 on L1 - TOP "NONET_L-01_P-001" (solid, pour order 659): 30.233,181.491 31.283,181.491 31.583,181.791 31.583,183.691 31.958,184.066 40.033,184.066 40.408,184.441 40.408,196.341 39.158,197.591 29.058,197.591 28.533,197.066 28.533,196.516 29.558,195.491 29.558,184.416 30.233,183.741
NetD2_3_A on L1 - TOP "NONET_L-01_P-001" (solid, pour order 655): 22.008,190.766 23.233,191.991 23.233,197.866 24.408,199.041 27.458,199.041 28.208,198.291 28.208,186.041 27.958,185.791 15.158,185.791 14.783,186.166 14.783,190.341 15.208,190.766
GND on L1 - TOP "NONET_L-01_P-001" (solid, pour order 667): 25.529,176.466 25.283,176.712 25.283,180.116 25.958,180.791 29.233,180.791 29.858,180.166 29.858,179.016 30.008,178.866 31.158,178.866 31.408,178.616 31.408,178.216 31.283,178.091 29.858,178.091 29.608,177.841 29.608,176.991 29.083,176.466
GND on L1 - TOP "NONET_L-01_P-001" (solid, pour order 663): 12.125,200.049 12.125,204.83 13.786,206.491 38.533,206.491 40.008,205.016 40.008,198.941 39.183,198.116 29.008,198.116 28.583,198.541 28.583,199.591 28.083,200.091 24.308,200.091 21.033,196.816 15.358,196.816
+5V on L1 - TOP "NONET_L-01_P-001" (solid, pour order 753): 40.875,191.655 41.85,192.63 48.175,192.63 48.3,192.505 48.3,190.83 48.075,190.605 41.25,190.605 40.875,190.98
GND on L1 - TOP "NONET_L-01_P-001" (solid, pour order 757): 54.225,196.905 54.325,197.005 54.6,197.005 54.7,196.905 54.7,195.43 56.725,193.405 56.725,188.155 56.275,187.705 42.975,187.705 42.6,188.08 42.6,189.68 43,190.08 50.725,190.08 51.125,190.48 51.125,192.53 51.2,192.605 52,192.605 52.1,192.505 52.1,191.58 52.3,191.38 54.65,191.38 55.15,191.88 55.15,193.43 54.225,194.355
GND on L1 - TOP "NONET_L-01_P-001" (solid, pour order 761): 54.1,201.88 54.3,201.68 60.45,201.68 60.7,201.93 60.7,205.455 59.975,206.18 54.2,206.18 54.1,206.08
3V3 on L1 - TOP "NONET_L-01_P-001" (solid, pour order 765): 50.225,205.855 50.525,206.155 53.25,206.155 53.425,205.98 53.425,199.73 53.3,199.605 53,199.605 52.925,199.68 52.925,201.43 52.65,201.705 50.35,201.705 50.225,201.83
HALL_OUT_3 on L1 - TOP "NONET_L-01_P-001" (solid, pour order 769): 49.9,186.905 50.125,187.13 64.675,187.13 66.975,189.43 71.125,189.43 74.15,186.405 74.15,178.825 73.2,177.875 50.775,177.875 49.9,178.75
VLEAF_IN_3 on L1 - TOP "NONET_L-01_P-001" (solid, pour order 773): 49.525,186.88 49.325,187.08 40.95,187.08 40.3,187.73 39.3,187.73 38.825,187.255 38.825,184.38 39.139,184.066 49.261,184.066 49.525,184.33
VLEAF_IN_2 on L1 - TOP "NONET_L-01_P-001" (solid, pour order 658): 30.233,217.601 31.283,217.601 31.583,217.901 31.583,219.801 31.958,220.176 40.033,220.176 40.408,220.551 40.408,232.451 39.158,233.701 29.058,233.701 28.533,233.176 28.533,232.626 29.558,231.601 29.558,220.526 30.233,219.851
NetD2_2_A on L1 - TOP "NONET_L-01_P-001" (solid, pour order 654): 22.008,226.876 23.233,228.101 23.233,233.976 24.408,235.151 27.458,235.151 28.208,234.401 28.208,222.151 27.958,221.901 15.158,221.901 14.783,222.276 14.783,226.451 15.208,226.876
GND on L1 - TOP "NONET_L-01_P-001" (solid, pour order 666): 25.529,212.576 25.283,212.822 25.283,216.226 25.958,216.901 29.233,216.901 29.858,216.276 29.858,215.126 30.008,214.976 31.158,214.976 31.408,214.726 31.408,214.326 31.283,214.201 29.858,214.201 29.608,213.951 29.608,213.101 29.083,212.576
GND on L1 - TOP "NONET_L-01_P-001" (solid, pour order 662): 12.125,236.159 12.125,240.94 13.786,242.601 38.533,242.601 40.008,241.126 40.008,235.051 39.183,234.226 29.008,234.226 28.583,234.651 28.583,235.701 28.083,236.201 24.308,236.201 21.033,232.926 15.358,232.926
+5V on L1 - TOP "NONET_L-01_P-001" (solid, pour order 752): 40.875,227.765 41.85,228.74 48.175,228.74 48.3,228.615 48.3,226.94 48.075,226.715 41.25,226.715 40.875,227.09
GND on L1 - TOP "NONET_L-01_P-001" (solid, pour order 756): 54.225,233.015 54.325,233.115 54.6,233.115 54.7,233.015 54.7,231.54 56.725,229.515 56.725,224.265 56.275,223.815 42.975,223.815 42.6,224.19 42.6,225.79 43,226.19 50.725,226.19 51.125,226.59 51.125,228.64 51.2,228.715 52,228.715 52.1,228.615 52.1,227.69 52.3,227.49 54.65,227.49 55.15,227.99 55.15,229.54 54.225,230.465
GND on L1 - TOP "NONET_L-01_P-001" (solid, pour order 760): 54.1,237.99 54.3,237.79 60.45,237.79 60.7,238.04 60.7,241.565 59.975,242.29 54.2,242.29 54.1,242.19
3V3 on L1 - TOP "NONET_L-01_P-001" (solid, pour order 764): 50.225,241.965 50.525,242.265 53.25,242.265 53.425,242.09 53.425,235.84 53.3,235.715 53,235.715 52.925,235.79 52.925,237.54 52.65,237.815 50.35,237.815 50.225,237.94
HALL_OUT_2 on L1 - TOP "NONET_L-01_P-001" (solid, pour order 768): 49.9,223.015 50.125,223.24 64.675,223.24 66.975,225.54 71.125,225.54 74.15,222.515 74.15,214.725 72.85,213.425 51.25,213.425 49.9,214.775
VLEAF_IN_2 on L1 - TOP "NONET_L-01_P-001" (solid, pour order 772): 49.525,222.99 49.325,223.19 40.95,223.19 40.3,223.84 39.3,223.84 38.825,223.365 38.825,220.49 39.139,220.176 49.261,220.176 49.525,220.44
VLEAF_IN_1 on L1 - TOP "NONET_L-01_P-001" (solid, pour order 771): 49.525,259.1 49.325,259.3 40.95,259.3 40.3,259.95 39.3,259.95 38.825,259.475 38.825,256.6 39.139,256.286 49.261,256.286 49.525,256.55
HALL_OUT_1 on L1 - TOP "NONET_L-01_P-001" (solid, pour order 767): 49.9,259.125 50.125,259.35 61.775,259.35 64.1,261.675 71.1,261.675 74.15,258.625 74.15,251.525 72.825,250.2 51.25,250.2 49.9,251.55
3V3 on L1 - TOP "NONET_L-01_P-001" (solid, pour order 763): 50.225,278.075 50.525,278.375 53.25,278.375 53.425,278.2 53.425,271.95 53.3,271.825 53,271.825 52.925,271.9 52.925,273.65 52.65,273.925 50.35,273.925 50.225,274.05
GND on L1 - TOP "NONET_L-01_P-001" (solid, pour order 759): 54.1,274.1 54.3,273.9 60.45,273.9 60.7,274.15 60.7,277.675 59.975,278.4 54.2,278.4 54.1,278.3
GND on L1 - TOP "NONET_L-01_P-001" (solid, pour order 755): 54.225,269.125 54.325,269.225 54.6,269.225 54.7,269.125 54.7,267.65 56.725,265.625 56.725,260.375 56.275,259.925 42.975,259.925 42.6,260.3 42.6,261.9 43,262.3 50.725,262.3 51.125,262.7 51.125,264.75 51.2,264.825 52,264.825 52.1,264.725 52.1,263.8 52.3,263.6 54.65,263.6 55.15,264.1 55.15,265.65 54.225,266.575
+5V on L1 - TOP "NONET_L-01_P-001" (solid, pour order 751): 40.875,263.875 41.85,264.85 48.175,264.85 48.3,264.725 48.3,263.05 48.075,262.825 41.25,262.825 40.875,263.2
+12V on L1 - TOP "NONET_L-01_P-001" (solid, pour order 705): 194.275,265.075 194.575,264.775 196.3,264.775 196.425,264.9 196.425,267.3 196.325,267.4 194.425,267.4 194.275,267.25
GND on L1 - TOP "NONET_L-01_P-001" (solid, pour order 661): 12.125,272.269 12.125,277.05 13.375,278.3 38.944,278.3 40.008,277.236 40.008,271.161 39.183,270.336 29.008,270.336 28.583,270.761 28.583,271.811 28.083,272.311 24.308,272.311 21.033,269.036 15.358,269.036
NetC41_2 on L1 - TOP "NONET_L-01_P-001" (solid, pour order 741): 177.7,246.125 179.825,246.125 180.3,245.65 180.3,245.2 180.55,244.95 182.125,244.95 182.125,243.7 182.275,243.55 181.9,243.175 181.9,243.025 178.575,243.025 177.85,243.75 177.6,244 177.6,246.025
NetC39_1 on L1 - TOP "NONET_L-01_P-001" (solid, pour order 739): 189.325,253.526 189.499,253.7 191.9,253.7 192.3,253.3 192.3,247.925 192.275,247.9 191.475,247.9 191.45,247.925 191.45,250.637 191.387,250.7 189.525,250.7 189.325,250.9
3V3 on L1 - TOP "NONET_L-01_P-001" (solid, pour order 738): 139.8,251.6 140.1,251.6 140.9,252.4 142.2,252.4 142.6,252 142.6,251.1 142.1,250.6 140.5,250.6 140.075,250.175
GND on L1 - TOP "NONET_L-01_P-001" (solid, pour order 737): 197.6,270.4 198.4,271.2 200.4,271.2 200.5,271.1 200.5,270.1 200.5,267.85 200.15,267.5 197.7,267.5 197.6,267.6
CO_STACK_IN on L1 - TOP "NONET_L-01_P-001" (solid, pour order 730): 137.9,231.4 139.9,231.4 139.9,227.2 139.8,227.1 138,227.1 137.9,227.2
GND on L1 - TOP "NONET_L-01_P-001" (solid, pour order 708): 193.475,270.475 183.35,270.475 182.75,271.075 182.75,273.1 183.225,273.575 190.825,273.575 191.25,274 191.25,276.475 191.595,276.82 202.505,276.82 203.55,275.775 203.55,273.275 204.375,272.45 206.925,272.45 208.05,271.325 208.05,268.05 209,268.05 210.075,266.975 210.225,267.125 210.225,275.975 208.075,278.125 184.825,278.125 180.925,274.225 180.925,251.65 181.075,251.5 186.55,256.975 188.825,256.975 183.125,262.675 183.125,267.225 183.325,267.425 193.318,267.425
GND on L1 - TOP "NONET_L-01_P-001" (solid, pour order 673): 132.9,262.275 132.35,261.725 128.425,261.725 128.225,261.925 128.225,262.775 128.7,263.25 129.575,263.25 129.9,263.575 129.9,264.725 130.225,265.05 132.275,265.05 132.9,265.675 132.9,267.975 133.2,268.275 134.175,268.275 134.4,268.05 134.4,264.35 134.275,264.225 132.85,264.225 132.625,264 132.625,263.125 132.9,262.85
3V3 on L1 - TOP "NONET_L-01_P-001" (solid, pour order 672): 138.65,264.3 138.65,266 138.325,266.325 138.325,268.25 138.2,268.375 135.3,268.375 135,268.075 135,263.325 135.45,262.875 136.35,262.875 137.25,263.775 138.225,263.775
GND on L1 - TOP "NONET_L-01_P-001" (solid, pour order 711): 135.925,252.4 140.225,252.4 140.225,255.125 140.025,255.325 136.1,255.325 135.925,255.15
3V3 on L1 - TOP "NONET_L-01_P-001" (solid, pour order 710): 140.525,251.6 140.525,250.625 140.075,250.175 139.65,250.175 139.575,250.1 139.575,249.25 139.417,249.092 139.375,249.175 139.375,250.075 139.2,250.25 136,250.25 136,251.6
GND on L1 - TOP "NONET_L-01_P-001" (solid, pour order 665): 25.529,248.686 25.283,248.932 25.283,252.336 25.958,253.011 29.233,253.011 29.858,252.386 29.858,251.236 30.008,251.086 31.158,251.086 31.408,250.836 31.408,250.436 31.283,250.311 29.858,250.311 29.608,250.061 29.608,249.211 29.083,248.686
GND on L1 - TOP "NONET_L-01_P-001" (solid, pour order 669): 164.475,243.625 164.2,243.35 160.4,243.35 159.875,243.875 159.875,246.5 160.275,246.9 164.1,246.9 164.475,246.525
GND on L1 - TOP "NONET_L-01_P-001" (solid, pour order 670): 173.825,246.95 172.375,246.95 171.725,246.3 171.725,245.625 171.1,245 171.1,241.075 171.375,240.8 172.325,240.8 172.625,241.1 172.625,244.6 172.85,244.825 173.3,244.825 174.125,245.65 174.125,246.675
GND on L1 - TOP "NONET_L-01_P-001" (solid, pour order 679): 201.2,247.85 202.3,247.85 203.15,248.7 203.15,251.225 205.125,253.2 207.75,253.2 210.2,250.75 210.2,245.95 209,244.75 201.175,244.75
GND on L1 - TOP "NONET_L-01_P-001" (solid, pour order 706): 205.2,265.525 204.925,265.8 204.925,267.775 205.2,268.05 209.9,268.05 210.2,267.75 210.2,250.7 209.075,249.575 205.675,249.575 205.1,250.15 205.125,250.175 205.125,253.2 205.625,253.7 207.3,253.7 207.725,254.125 207.725,265.2 205.525,265.2 205.175,265.55
GND on L1 - TOP "NONET_L-01_P-001" (solid, pour order 707): 192.875,267.8 192.875,257.15 193.5,256.525 195.475,256.525 196.95,258 196.95,263.075 196.55,263.475 194.75,263.475 193.8,264.425 193.8,267.8
NetC46_2 on L1 - TOP "NONET_L-01_P-001" (solid, pour order 702): 193.075,274.65 192.95,274.775 192.425,274.775 192.175,275.025 192.175,276.525 192.325,276.675 193.35,276.675 193.55,276.475 193.55,273.475 193.675,273.35 193.675,272.525 193.25,272.525 193.075,272.7
NetC46_2 on L1 - TOP "NONET_L-01_P-001" (solid, pour order 709): 191.675,272.775 192.175,273.275 192.175,275.525 193.275,275.525 193.55,275.25 193.55,271.13 193.195,270.775 183.45,270.775 183.325,270.9 183.325,272.7 183.4,272.775
LIPO on L1 - TOP "NONET_L-01_P-001" (solid, pour order 704): 191.425,244.525 193.425,244.525 193.6,244.35 193.6,242.425 193.25,242.075 191.55,242.075 191.45,242.175
NetC50_1 on L1 - TOP "NONET_L-01_P-001" (solid, pour order 703): 191.15,257.75 191.475,258.075 191.475,266.75 190.975,267.25 183.45,267.25 183.25,267.05 183.25,262.821 188.359,257.713
NetC46_1 on L1 - TOP "NONET_L-01_P-001" (solid, pour order 701): 194.425,272.6 194.425,274.7 194.175,274.95 194.175,276.475 194.375,276.675 195.375,276.675 195.525,276.525 195.525,275 195.025,274.5 195.025,272.6 194.95,272.525 194.5,272.525
NetC39_2 on L1 - TOP "NONET_L-01_P-001" (solid, pour order 674): 183.95,249.975 184.55,249.975 185.45,250.875 185.45,253.35 185.9,253.8 188.338,253.8 188.575,253.563 188.575,250.55 188.95,250.175 190.595,250.175 190.595,248.025 187.675,248.025 187.575,247.925 187.575,247.725 187.45,247.6 184,247.6 183.875,247.725 183.875,249.9
NetR31_1 on L1 - TOP "NONET_L-01_P-001" (solid, pour order 675): 194.605,250.2 198,250.2 198.475,249.725 198.475,248.25 198.125,247.9 194.731,247.9 194.605,248.025
NetC41_2 on L1 - TOP "NONET_L-01_P-001" (solid, pour order 676): 178.241,232.184 177.6,232.825 177.6,244.4 178.15,244.95 188.325,244.95 188.975,244.3 188.975,232.125
LIPO on L1 - TOP "NONET_L-01_P-001" (solid, pour order 678): 192.5,232.625 191.1,231.225 167.925,231.225 167,230.3 167,225.875 167.175,225.7 191.8,225.7 202.15,225.7 203.7,227.25 210.35,227.25 210.95,227.85 210.95,241.575 210.5,242.025 200.8,242.025 198.35,239.575 198.35,232.9 198.075,232.625
NetD2_1_A on L1 - TOP "NONET_L-01_P-001" (solid, pour order 653): 22.008,262.986 23.233,264.211 23.233,270.086 24.408,271.261 27.458,271.261 28.208,270.511 28.208,258.261 27.958,258.011 15.158,258.011 14.783,258.386 14.783,262.561 15.208,262.986
3V3 on L1 - TOP "NONET_L-01_P-001" (solid, pour order 671): 170.075,246.95 168.9,246.95 168.45,246.5 168.45,245.775 168.1,245.425 167.075,245.425 166.925,245.275 166.925,244.45 167.15,244.225 168.35,244.225 168.675,243.9 168.675,241.3 169.025,240.95 170.1,240.95 170.45,241.3 170.45,246.625 170.35,246.725
GND on L2 - GND "NONET_L-01_P-001" (solid, pour order 718): 11.3,277.9 12.111,278.711 209.389,278.711 210.8,277.3 210.8,135.8 208.4,133.4 13.1,133.4 11.3,135.2

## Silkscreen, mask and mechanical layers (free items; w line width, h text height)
Top Overlay:
  drawing of 629 lines, arcs and shapes, not listed
  text "REF_HALL" at 136.154,275.98 h1
  text "E5V" at 177.529,273.604 h1
  text "5V" at 202.8,263.104 h1
  text "12V" at 202.8,257.954 h1
  text "E12V" at 176.696,255.329 h1
  text "IL1" at 60.929,250.779 h1.52
  text "VIN1" at 34.912,246.729 h1.52
  text "LIPO OUT" at 201.479,235.554 h1
  text "VI4" at 128.45,215.475 h1
  text "VI3" at 132.6,215.475 h1
  text "Designed by Davide Catania 342775." at 165.525,215.325 h1
  text "Politecnico di Torino - December 2026" at 172.779,212.8 h1
  text "VI1" at 128.68,212.2 h1
  text "VI2" at 132.6,212.2 h1
  text "IL1" at 138.6,212.2 h1
  text "VIN2" at 34.479,210.379 h1.52
  text "IL2" at 60.929,208.779 h1.52
  text "IL3" at 60.929,178.454 h1.52
  text "VIN3" at 34.404,174.254 h1.52
  text "PWM2" at 135.4,148.425 h1
  text "PWM1" at 148.05,148.425 h1
  text "IL3" at 158.492,148.425 h1
  text "IL2" at 161.675,148.425 h1
  text "IL4" at 60.929,142.054 h1.52
  text "IL4" at 135.41,141.95 h1
  text "PWM4" at 142.713,141.95 h1
  text "IO" at 151.675,141.95 h1
  text "PWM3" at 158,141.95 h1
  text "VO" at 171.775,141.95 h1
  text "Supervisor: Erica Raviola" at 169.304,138.437 h1
  text "VIN4" at 34.404,138.279 h1.52
  text "Co-supervisor: Carlos Sanchez Diaz" at 169.304,135.887 h1
Mechanical 1:
  lines w0.254: 10.85,169.625 cw(c12.12,169.625) 12.12,170.895 ; 10.85,205.735 cw(c12.12,205.735) 12.12,207.005 ; 10.85,241.845 cw(c12.12,241.845) 12.12,243.115 ; 209.798,276.952 209.802,276.948 ; 10.85,133.29 ccw(c12.12,133.29) 12.12,132.02 cw(c12.125,132.02) 12.125,132.025 13.375,132.025 210.305,132.025 ccw(c210.305,133.295) 211.575,133.295 211.575,277.955 ccw(c210.305,277.955) 210.305,279.225 12.12,279.225 ccw(c12.12,277.955) 10.85,277.955 10.85,133.29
